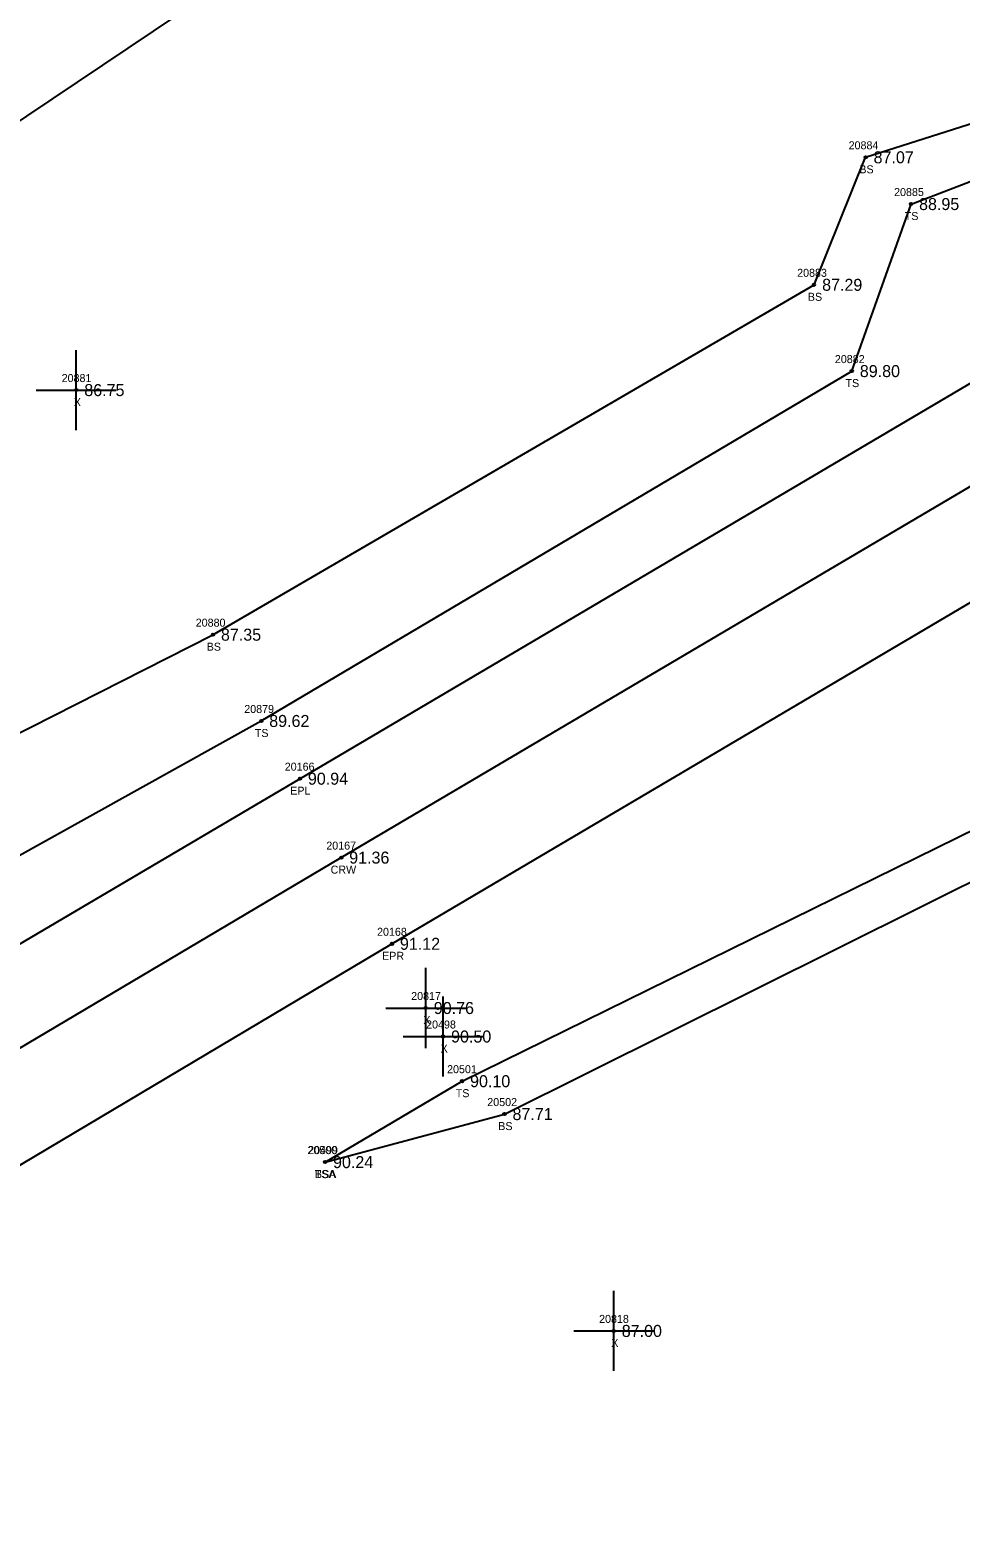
# Model space of a CAD drawing. Extents: x 2530197 to 2532051, y 935230 to 936631.
# Drawn here: x 2531258.3 to 2531374.5, y 935982 to 936167.6 of the extents above; entities that cross this region are included whole.
import ezdxf

# ---------------------------------------------------------------- set-up
doc = ezdxf.new("R2010")
doc.units = 0
for name, color, linetype in [('RD_DTM_BkLn1', 7, 'Continuous'), ('RD_DTM_BkLn2', 7, 'Continuous'), ('RD_DTM_BkLn_txCode', 7, 'Continuous'), ('RD_EX_Misc', 7, 'Continuous'), ('RD_EX_Misc_txCode', 7, 'Continuous'), ('RD_EX_Road', 7, 'Continuous'), ('RD_EX_Road_txCode', 7, 'Continuous'), ('RD_EX_TX_Misc_ELEV', 7, 'Continuous'), ('RD_EX_TX_Road_ELEV', 7, 'Continuous'), ('RD_HC_Survey_ELEV', 7, 'Continuous'), ('RD_HC_Survey_txCode', 7, 'Continuous'), ('RD_SMD_Locator', 7, 'Continuous')]:
    doc.layers.add(name, color=color, linetype=linetype)

msp = doc.modelspace()

# ---------------------------------------------------------------- linework, layer by layer
at = {"layer": 'RD_DTM_BkLn1'}
msp.add_lwpolyline([(2531175.16, 935992.09), (2531214.08, 936014.93), (2531297.2, 936064.16), (2531382.2, 936114.3), (2531466.12, 936163.77), (2531548.89, 936212.96), (2531632.55, 936261.89), (2531678, 936289.19), (2531722.34, 936315.93), (2531754.26, 936342.49), (2531759.78, 936349.83), (2531772.77, 936373.29), (2531778.96, 936389.71), (2531793.78, 936438.29), (2531813.65, 936511.36), (2531832.39, 936582.88)], dxfattribs=at)
at = {"layer": 'RD_DTM_BkLn2'}
for points in [[(2531232.8, 936067.46), (2531215.52, 936108.97), (2531226.2, 936132.67), (2531251.54, 936152.54), (2531308.69, 936190.88), (2531325.04, 936186.59), (2531344.92, 936198.09), (2531350.73, 936212.74), (2531384.02, 936231.34), (2531448.45, 936270.32)], [(2531232.8, 936067.46), (2531281.18, 936092.01), (2531356.28, 936135.72), (2531362.71, 936151.65), (2531400.38, 936163.66), (2531430.03, 936179.35), (2531446.05, 936177.07), (2531452.65, 936188.16), (2531481.32, 936210.45), (2531494.44, 936219.29)], [(2531229.61, 936049.23), (2531287.21, 936081.23), (2531360.99, 936124.94), (2531368.39, 936145.81), (2531399.09, 936157.58), (2531431.15, 936172.97), (2531448.86, 936171.41), (2531455.43, 936183.06), (2531483.94, 936207.52), (2531496.93, 936216.06)], [(2531295.18, 936026.12), (2531312.3, 936036.23), (2531402.53, 936080.62), (2531437.6, 936110.11), (2531444.57, 936114.24), (2531446.06, 936117.79), (2531450.6, 936121.06), (2531460.51, 936128.61), (2531463.31, 936137.14), (2531463.91, 936139.69), (2531469.69, 936142.11), (2531476.37, 936143.57), (2531477.33, 936143.53), (2531478.69, 936136.4), (2531501.93, 936140.05), (2531521.67, 936152.11)], [(2531295.18, 936026.12), (2531317.6, 936032.12), (2531401.15, 936073.7), (2531462.84, 936126.42), (2531466.9, 936128.09), (2531468.72, 936130.63), (2531466.13, 936132.91), (2531477.41, 936138.74), (2531476.94, 936135.81), (2531477.06, 936134.1), (2531481.14, 936135.21), (2531503.77, 936136.95), (2531524.91, 936150.29)]]:
    msp.add_lwpolyline(points, dxfattribs=at)
at = {"layer": 'RD_EX_Misc'}
for p, q in [((2531264.11, 936117.57), (2531264.11, 936127.57)), ((2531259.11, 936122.57), (2531269.11, 936122.57)), ((2531307.77, 936040.37), (2531307.77, 936050.37)), ((2531309.93, 936036.81), (2531309.93, 936046.81)), ((2531302.77, 936045.37), (2531312.77, 936045.37)), ((2531304.93, 936041.81), (2531314.93, 936041.81)), ((2531331.25, 936000.03), (2531331.25, 936010.03)), ((2531326.25, 936005.03), (2531336.25, 936005.03))]:
    msp.add_line(p, q, dxfattribs=at)
at = {"layer": 'RD_EX_Road'}
for points in [[(2531169.65, 936000.77), (2531208.79, 936024.95), (2531292.04, 936074.02), (2531376.24, 936123.7), (2531460.37, 936174.49), (2531542.92, 936223.44), (2531626.67, 936270.85), (2531672.4, 936298.39), (2531714.28, 936327.21), (2531747.19, 936360.45), (2531761.42, 936377.32), (2531773.11, 936411.11), (2531782.2, 936441.65), (2531803.17, 936514.76), (2531820.28, 936585.8)], [(2531180.82, 935982), (2531220.82, 936004.21), (2531303.54, 936053.39), (2531388.75, 936103.71), (2531472.27, 936152.98), (2531554.79, 936201.9), (2531638.11, 936250.92), (2531683.19, 936278.28), (2531730.37, 936304.55), (2531771.5, 936341.26), (2531788.67, 936375.53), (2531805.57, 936434.84), (2531825.53, 936508.74), (2531844.13, 936579.65)]]:
    msp.add_lwpolyline(points, dxfattribs=at)
at = {"layer": 'RD_SMD_Locator'}
for centre in [(2531362.71, 936151.65), (2531368.39, 936145.81), (2531356.28, 936135.72), (2531360.99, 936124.94), (2531264.11, 936122.57), (2531281.18, 936092.01), (2531287.21, 936081.23), (2531292.04, 936074.02), (2531297.2, 936064.16), (2531303.54, 936053.39), (2531307.77, 936045.37), (2531309.93, 936041.81), (2531312.3, 936036.23), (2531317.6, 936032.12), (2531295.18, 936026.12), (2531295.18, 936026.12), (2531331.25, 936005.03)]:
    msp.add_circle(centre, 0.15, dxfattribs=at)

# ---------------------------------------------------------------- texts
at = {"layer": 'RD_DTM_BkLn_txCode'}
for s, p in [('20884', (2531360.59, 936152.65)), ('BS', (2531361.93, 936149.65)), ('20885', (2531366.27, 936146.81)), ('TS', (2531367.6, 936143.81)), ('20883', (2531354.16, 936136.72)), ('BS', (2531355.5, 936133.72)), ('20882', (2531358.87, 936125.94)), ('TS', (2531360.2, 936122.94)), ('20880', (2531279.03, 936093.01)), ('BS', (2531280.4, 936090.01)), ('20879', (2531285.09, 936082.23)), ('TS', (2531286.41, 936079.23)), ('20501', (2531310.43, 936037.23)), ('TS', (2531311.51, 936034.23)), ('20502', (2531315.45, 936033.12)), ('BS', (2531316.82, 936030.12)), ('20500', (2531292.99, 936027.12)), ('20499', (2531293.07, 936027.12)), ('TSA', (2531293.9, 936024.12)), ('BSA', (2531293.92, 936024.12))]:
    msp.add_text(s, height=1, dxfattribs=at).set_placement(p)
at = {"layer": 'RD_EX_Misc_txCode'}
for s, p in [('20881', (2531262.28, 936123.57)), ('X', (2531263.8, 936120.57)), ('20817', (2531305.94, 936046.37)), ('X', (2531307.46, 936043.37)), ('20498', (2531307.81, 936042.81)), ('X', (2531309.62, 936039.81)), ('20818', (2531329.42, 936006.03)), ('X', (2531330.94, 936003.03))]:
    msp.add_text(s, height=1, dxfattribs=at).set_placement(p)
at = {"layer": 'RD_EX_Road_txCode'}
for s, p in [('20166', (2531290.15, 936075.02)), ('EPL', (2531290.83, 936072.02)), ('20168', (2531301.68, 936054.39)), ('EPR', (2531302.31, 936051.39))]:
    msp.add_text(s, height=1, dxfattribs=at).set_placement(p)
at = {"layer": 'RD_EX_TX_Misc_ELEV'}
for s, p in [('87.07', (2531363.71, 936150.9)), ('88.95', (2531369.39, 936145.06)), ('87.29', (2531357.28, 936134.97)), ('89.80', (2531361.99, 936124.19)), ('86.75', (2531265.11, 936121.82)), ('87.35', (2531282.18, 936091.26)), ('89.62', (2531288.21, 936080.48)), ('90.76', (2531308.77, 936044.62)), ('90.50', (2531310.93, 936041.06)), ('90.10', (2531313.3, 936035.48)), ('87.71', (2531318.6, 936031.37)), ('90.24', (2531296.18, 936025.37)), ('90.24', (2531296.18, 936025.37)), ('87.00', (2531332.25, 936004.28))]:
    msp.add_text(s, height=1.5, dxfattribs=at).set_placement(p)
at = {"layer": 'RD_EX_TX_Road_ELEV'}
for s, p in [('90.94', (2531293.04, 936073.27)), ('91.12', (2531304.54, 936052.64))]:
    msp.add_text(s, height=1.5, dxfattribs=at).set_placement(p)
at = {"layer": 'RD_HC_Survey_ELEV'}
msp.add_text('91.36', height=1.5, dxfattribs=at).set_placement((2531298.2, 936063.41))
at = {"layer": 'RD_HC_Survey_txCode'}
for s, p in [('20167', (2531295.34, 936065.16)), ('CRW', (2531295.88, 936062.16))]:
    msp.add_text(s, height=1, dxfattribs=at).set_placement(p)

doc.saveas('drawing.dxf')
